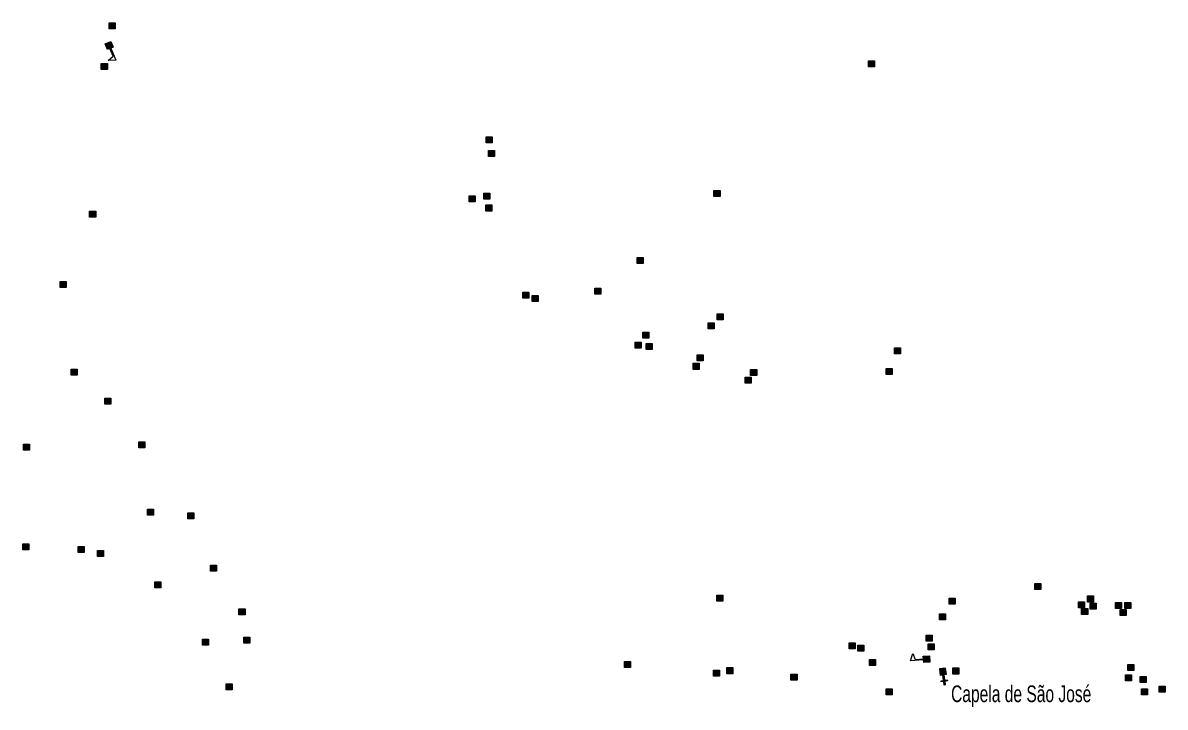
# Model space of a CAD drawing. Extents: x 649.2 to 674.4, y 7040 to 7068.1.
# Drawn here: x 656.02 to 661.51, y 7043.6 to 7046.89 of the extents above; entities that cross this region are included whole.
import ezdxf

# ---------------------------------------------------------------- set-up
doc = ezdxf.new("R2010")
doc.units = 0
doc.header["$LTSCALE"] = 0.032
for name, color, linetype, lineweight in [('2', 7, 'Continuous', 25), ('4', 7, 'Continuous', 25), ('6', 7, 'Continuous', 25)]:
    doc.layers.add(name, color=color, linetype=linetype, lineweight=lineweight)
doc.layers.add('61', color=7, linetype='Continuous')

msp = doc.modelspace()

# ---------------------------------------------------------------- hatches: boundary and pattern name
at = {"layer": '2'}
for points in [[(656.4322, 7046.8861), (656.4612, 7046.8861), (656.4612, 7046.8571), (656.4322, 7046.8571)], [(660.0846, 7046.7032), (660.1136, 7046.7032), (660.1136, 7046.6742), (660.0846, 7046.6742)], [(656.3943, 7046.6907), (656.4233, 7046.6907), (656.4233, 7046.6617), (656.3943, 7046.6617)], [(658.2456, 7046.3383), (658.2746, 7046.3383), (658.2746, 7046.3093), (658.2456, 7046.3093)], [(658.257, 7046.2729), (658.286, 7046.2729), (658.286, 7046.2439), (658.257, 7046.2439)], [(658.1636, 7046.0539), (658.1926, 7046.0539), (658.1926, 7046.0249), (658.1636, 7046.0249)], [(658.2342, 7046.0674), (658.2632, 7046.0674), (658.2632, 7046.0384), (658.2342, 7046.0384)], [(659.3413, 7046.0802), (659.3703, 7046.0802), (659.3703, 7046.0512), (659.3413, 7046.0512)], [(658.2445, 7046.0104), (658.2735, 7046.0104), (658.2735, 7045.9814), (658.2445, 7045.9814)], [(656.3381, 7045.9813), (656.3671, 7045.9813), (656.3671, 7045.9523), (656.3381, 7045.9523)], [(658.9721, 7045.7574), (659.0011, 7045.7574), (659.0011, 7045.7284), (658.9721, 7045.7284)], [(656.1956, 7045.6419), (656.2246, 7045.6419), (656.2246, 7045.6129), (656.1956, 7045.6129)], [(658.7686, 7045.6101), (658.7976, 7045.6101), (658.7976, 7045.5811), (658.7686, 7045.5811)], [(658.4223, 7045.5913), (658.4513, 7045.5913), (658.4513, 7045.5623), (658.4223, 7045.5623)], [(658.4665, 7045.5755), (658.4955, 7045.5755), (658.4955, 7045.5465), (658.4665, 7045.5465)], [(659.3134, 7045.4445), (659.3424, 7045.4445), (659.3424, 7045.4155), (659.3134, 7045.4155)], [(659.3561, 7045.4872), (659.3851, 7045.4872), (659.3851, 7045.4582), (659.3561, 7045.4582)], [(658.9988, 7045.3983), (659.0278, 7045.3983), (659.0278, 7045.3693), (658.9988, 7045.3693)], [(658.9615, 7045.3503), (658.9905, 7045.3503), (658.9905, 7045.3213), (658.9615, 7045.3213)], [(659.0148, 7045.345), (659.0438, 7045.345), (659.0438, 7045.316), (659.0148, 7045.316)], [(660.2099, 7045.3236), (660.2389, 7045.3236), (660.2389, 7045.2946), (660.2099, 7045.2946)], [(659.2601, 7045.2899), (659.2891, 7045.2899), (659.2891, 7045.2609), (659.2601, 7045.2609)], [(656.2492, 7045.2208), (656.2782, 7045.2208), (656.2782, 7045.1918), (656.2492, 7045.1918)], [(659.2405, 7045.249), (659.2695, 7045.249), (659.2695, 7045.22), (659.2405, 7045.22)], [(659.5178, 7045.2188), (659.5468, 7045.2188), (659.5468, 7045.1898), (659.5178, 7045.1898)], [(660.1698, 7045.2245), (660.1988, 7045.2245), (660.1988, 7045.1955), (660.1698, 7045.1955)], [(659.4912, 7045.1832), (659.5202, 7045.1832), (659.5202, 7045.1542), (659.4912, 7045.1542)], [(656.4106, 7045.0809), (656.4396, 7045.0809), (656.4396, 7045.0519), (656.4106, 7045.0519)], [(656.0198, 7044.8607), (656.0488, 7044.8607), (656.0488, 7044.8317), (656.0198, 7044.8317)], [(656.5748, 7044.8712), (656.6038, 7044.8712), (656.6038, 7044.8422), (656.5748, 7044.8422)], [(656.617, 7044.548), (656.646, 7044.548), (656.646, 7044.519), (656.617, 7044.519)], [(656.8105, 7044.5296), (656.8395, 7044.5296), (656.8395, 7044.5006), (656.8105, 7044.5006)], [(656.0168, 7044.3813), (656.0458, 7044.3813), (656.0458, 7044.3523), (656.0168, 7044.3523)], [(656.2822, 7044.3681), (656.3112, 7044.3681), (656.3112, 7044.3391), (656.2822, 7044.3391)], [(656.3757, 7044.3496), (656.4047, 7044.3496), (656.4047, 7044.3206), (656.3757, 7044.3206)], [(656.9187, 7044.2781), (656.9477, 7044.2781), (656.9477, 7044.2491), (656.9187, 7044.2491)], [(656.6519, 7044.1983), (656.6809, 7044.1983), (656.6809, 7044.1693), (656.6519, 7044.1693)], [(660.8851, 7044.1906), (660.9141, 7044.1906), (660.9141, 7044.1616), (660.8851, 7044.1616)], [(659.3543, 7044.1338), (659.3833, 7044.1338), (659.3833, 7044.1048), (659.3543, 7044.1048)], [(660.473, 7044.1199), (660.502, 7044.1199), (660.502, 7044.0909), (660.473, 7044.0909)], [(661.1374, 7044.1304), (661.1664, 7044.1304), (661.1664, 7044.1014), (661.1374, 7044.1014)], [(657.0565, 7044.0681), (657.0855, 7044.0681), (657.0855, 7044.0391), (657.0565, 7044.0391)], [(661.0943, 7044.1017), (661.1233, 7044.1017), (661.1233, 7044.0727), (661.0943, 7044.0727)], [(661.11, 7044.0703), (661.139, 7044.0703), (661.139, 7044.0413), (661.11, 7044.0413)], [(661.1505, 7044.0964), (661.1795, 7044.0964), (661.1795, 7044.0674), (661.1505, 7044.0674)], [(661.2721, 7044.0991), (661.3011, 7044.0991), (661.3011, 7044.0701), (661.2721, 7044.0701)], [(661.2957, 7044.0651), (661.3247, 7044.0651), (661.3247, 7044.0361), (661.2957, 7044.0361)], [(661.3179, 7044.0991), (661.3469, 7044.0991), (661.3469, 7044.0701), (661.3179, 7044.0701)], [(660.4258, 7044.0453), (660.4548, 7044.0453), (660.4548, 7044.0163), (660.4258, 7044.0163)], [(656.8809, 7043.9231), (656.9099, 7043.9231), (656.9099, 7043.8941), (656.8809, 7043.8941)], [(657.0804, 7043.9327), (657.1094, 7043.9327), (657.1094, 7043.9037), (657.0804, 7043.9037)], [(659.9916, 7043.9047), (660.0206, 7043.9047), (660.0206, 7043.8757), (659.9916, 7043.8757)], [(660.3623, 7043.942), (660.3913, 7043.942), (660.3913, 7043.913), (660.3623, 7043.913)], [(660.371, 7043.901), (660.4, 7043.901), (660.4, 7043.872), (660.371, 7043.872)], [(660.0327, 7043.8935), (660.0617, 7043.8935), (660.0617, 7043.8645), (660.0327, 7043.8645)], [(658.9113, 7043.8151), (658.9403, 7043.8151), (658.9403, 7043.7861), (658.9113, 7043.7861)], [(659.4033, 7043.7858), (659.4323, 7043.7858), (659.4323, 7043.7568), (659.4033, 7043.7568)], [(660.0899, 7043.8251), (660.1189, 7043.8251), (660.1189, 7043.7961), (660.0899, 7043.7961)], [(661.3323, 7043.8009), (661.3613, 7043.8009), (661.3613, 7043.7719), (661.3323, 7043.7719)], [(659.3392, 7043.7736), (659.3682, 7043.7736), (659.3682, 7043.7446), (659.3392, 7043.7446)], [(659.7117, 7043.7547), (659.7407, 7043.7547), (659.7407, 7043.7257), (659.7117, 7043.7257)], [(660.4905, 7043.7841), (660.5195, 7043.7841), (660.5195, 7043.7551), (660.4905, 7043.7551)], [(661.3205, 7043.7512), (661.3495, 7043.7512), (661.3495, 7043.7222), (661.3205, 7043.7222)], [(661.3911, 7043.7434), (661.4201, 7043.7434), (661.4201, 7043.7144), (661.3911, 7043.7144)], [(656.9948, 7043.7086), (657.0238, 7043.7086), (657.0238, 7043.6796), (656.9948, 7043.6796)], [(660.1695, 7043.6845), (660.1985, 7043.6845), (660.1985, 7043.6555), (660.1695, 7043.6555)], [(661.3976, 7043.6833), (661.4266, 7043.6833), (661.4266, 7043.6543), (661.3976, 7043.6543)], [(661.4826, 7043.6963), (661.5116, 7043.6963), (661.5116, 7043.6673), (661.4826, 7043.6673)]]:
    msp.add_hatch(color=256, dxfattribs=at).paths.add_polyline_path(points)
at = {"layer": '4'}
for points in [[(656.4403, 7046.7965), (656.452, 7046.7688), (656.4244, 7046.7572), (656.4127, 7046.7848)], [(660.3804, 7043.8126), (660.3505, 7043.8105), (660.3483, 7043.8404), (660.3782, 7043.8426)]]:
    msp.add_hatch(color=256, dxfattribs=at).paths.add_polyline_path(points)
at = {"layer": '6'}
for points in [[(660.4594, 7043.7538), (660.4552, 7043.7835), (660.4255, 7043.7793), (660.4297, 7043.7496)], [(660.442, 7043.7514), (660.447, 7043.7521), (660.4508, 7043.7248), (660.4632, 7043.7266), (660.4639, 7043.7216), (660.4515, 7043.7199), (660.454, 7043.7026), (660.449, 7043.7019), (660.4466, 7043.7192), (660.4342, 7043.7174), (660.4335, 7043.7224), (660.4459, 7043.7241)]]:
    msp.add_hatch(color=256, dxfattribs=at).paths.add_polyline_path(points)

# ---------------------------------------------------------------- linework, layer by layer
at = {"layer": '2'}
for points in [[(656.4322, 7046.8861), (656.4612, 7046.8861), (656.4612, 7046.8571), (656.4322, 7046.8571)], [(660.0846, 7046.7032), (660.1136, 7046.7032), (660.1136, 7046.6742), (660.0846, 7046.6742)], [(656.3943, 7046.6907), (656.4233, 7046.6907), (656.4233, 7046.6617), (656.3943, 7046.6617)], [(658.2456, 7046.3383), (658.2746, 7046.3383), (658.2746, 7046.3093), (658.2456, 7046.3093)], [(658.257, 7046.2729), (658.286, 7046.2729), (658.286, 7046.2439), (658.257, 7046.2439)], [(658.1636, 7046.0539), (658.1926, 7046.0539), (658.1926, 7046.0249), (658.1636, 7046.0249)], [(658.2342, 7046.0674), (658.2632, 7046.0674), (658.2632, 7046.0384), (658.2342, 7046.0384)], [(659.3413, 7046.0802), (659.3703, 7046.0802), (659.3703, 7046.0512), (659.3413, 7046.0512)], [(658.2445, 7046.0104), (658.2735, 7046.0104), (658.2735, 7045.9814), (658.2445, 7045.9814)], [(656.3381, 7045.9813), (656.3671, 7045.9813), (656.3671, 7045.9523), (656.3381, 7045.9523)], [(658.9721, 7045.7574), (659.0011, 7045.7574), (659.0011, 7045.7284), (658.9721, 7045.7284)], [(656.1956, 7045.6419), (656.2246, 7045.6419), (656.2246, 7045.6129), (656.1956, 7045.6129)], [(658.7686, 7045.6101), (658.7976, 7045.6101), (658.7976, 7045.5811), (658.7686, 7045.5811)], [(658.4223, 7045.5913), (658.4513, 7045.5913), (658.4513, 7045.5623), (658.4223, 7045.5623)], [(658.4665, 7045.5755), (658.4955, 7045.5755), (658.4955, 7045.5465), (658.4665, 7045.5465)], [(659.3134, 7045.4445), (659.3424, 7045.4445), (659.3424, 7045.4155), (659.3134, 7045.4155)], [(659.3561, 7045.4872), (659.3851, 7045.4872), (659.3851, 7045.4582), (659.3561, 7045.4582)], [(658.9988, 7045.3983), (659.0278, 7045.3983), (659.0278, 7045.3693), (658.9988, 7045.3693)], [(658.9615, 7045.3503), (658.9905, 7045.3503), (658.9905, 7045.3213), (658.9615, 7045.3213)], [(659.0148, 7045.345), (659.0438, 7045.345), (659.0438, 7045.316), (659.0148, 7045.316)], [(660.2099, 7045.3236), (660.2389, 7045.3236), (660.2389, 7045.2946), (660.2099, 7045.2946)], [(659.2601, 7045.2899), (659.2891, 7045.2899), (659.2891, 7045.2609), (659.2601, 7045.2609)], [(656.2492, 7045.2208), (656.2782, 7045.2208), (656.2782, 7045.1918), (656.2492, 7045.1918)], [(659.2405, 7045.249), (659.2695, 7045.249), (659.2695, 7045.22), (659.2405, 7045.22)], [(659.5178, 7045.2188), (659.5468, 7045.2188), (659.5468, 7045.1898), (659.5178, 7045.1898)], [(660.1698, 7045.2245), (660.1988, 7045.2245), (660.1988, 7045.1955), (660.1698, 7045.1955)], [(659.4912, 7045.1832), (659.5202, 7045.1832), (659.5202, 7045.1542), (659.4912, 7045.1542)], [(656.4106, 7045.0809), (656.4396, 7045.0809), (656.4396, 7045.0519), (656.4106, 7045.0519)], [(656.0198, 7044.8607), (656.0488, 7044.8607), (656.0488, 7044.8317), (656.0198, 7044.8317)], [(656.5748, 7044.8712), (656.6038, 7044.8712), (656.6038, 7044.8422), (656.5748, 7044.8422)], [(656.617, 7044.548), (656.646, 7044.548), (656.646, 7044.519), (656.617, 7044.519)], [(656.8105, 7044.5296), (656.8395, 7044.5296), (656.8395, 7044.5006), (656.8105, 7044.5006)], [(656.0168, 7044.3813), (656.0458, 7044.3813), (656.0458, 7044.3523), (656.0168, 7044.3523)], [(656.2822, 7044.3681), (656.3112, 7044.3681), (656.3112, 7044.3391), (656.2822, 7044.3391)], [(656.3757, 7044.3496), (656.4047, 7044.3496), (656.4047, 7044.3206), (656.3757, 7044.3206)], [(656.9187, 7044.2781), (656.9477, 7044.2781), (656.9477, 7044.2491), (656.9187, 7044.2491)], [(656.6519, 7044.1983), (656.6809, 7044.1983), (656.6809, 7044.1693), (656.6519, 7044.1693)], [(660.8851, 7044.1906), (660.9141, 7044.1906), (660.9141, 7044.1616), (660.8851, 7044.1616)], [(659.3543, 7044.1338), (659.3833, 7044.1338), (659.3833, 7044.1048), (659.3543, 7044.1048)], [(660.473, 7044.1199), (660.502, 7044.1199), (660.502, 7044.0909), (660.473, 7044.0909)], [(661.1374, 7044.1304), (661.1664, 7044.1304), (661.1664, 7044.1014), (661.1374, 7044.1014)], [(657.0565, 7044.0681), (657.0855, 7044.0681), (657.0855, 7044.0391), (657.0565, 7044.0391)], [(661.0943, 7044.1017), (661.1233, 7044.1017), (661.1233, 7044.0727), (661.0943, 7044.0727)], [(661.11, 7044.0703), (661.139, 7044.0703), (661.139, 7044.0413), (661.11, 7044.0413)], [(661.1505, 7044.0964), (661.1795, 7044.0964), (661.1795, 7044.0674), (661.1505, 7044.0674)], [(661.2721, 7044.0991), (661.3011, 7044.0991), (661.3011, 7044.0701), (661.2721, 7044.0701)], [(661.2957, 7044.0651), (661.3247, 7044.0651), (661.3247, 7044.0361), (661.2957, 7044.0361)], [(661.3179, 7044.0991), (661.3469, 7044.0991), (661.3469, 7044.0701), (661.3179, 7044.0701)], [(660.4258, 7044.0453), (660.4548, 7044.0453), (660.4548, 7044.0163), (660.4258, 7044.0163)], [(656.8809, 7043.9231), (656.9099, 7043.9231), (656.9099, 7043.8941), (656.8809, 7043.8941)], [(657.0804, 7043.9327), (657.1094, 7043.9327), (657.1094, 7043.9037), (657.0804, 7043.9037)], [(659.9916, 7043.9047), (660.0206, 7043.9047), (660.0206, 7043.8757), (659.9916, 7043.8757)], [(660.3623, 7043.942), (660.3913, 7043.942), (660.3913, 7043.913), (660.3623, 7043.913)], [(660.371, 7043.901), (660.4, 7043.901), (660.4, 7043.872), (660.371, 7043.872)], [(660.0327, 7043.8935), (660.0617, 7043.8935), (660.0617, 7043.8645), (660.0327, 7043.8645)], [(658.9113, 7043.8151), (658.9403, 7043.8151), (658.9403, 7043.7861), (658.9113, 7043.7861)], [(659.4033, 7043.7858), (659.4323, 7043.7858), (659.4323, 7043.7568), (659.4033, 7043.7568)], [(660.0899, 7043.8251), (660.1189, 7043.8251), (660.1189, 7043.7961), (660.0899, 7043.7961)], [(661.3323, 7043.8009), (661.3613, 7043.8009), (661.3613, 7043.7719), (661.3323, 7043.7719)], [(659.3392, 7043.7736), (659.3682, 7043.7736), (659.3682, 7043.7446), (659.3392, 7043.7446)], [(659.7117, 7043.7547), (659.7407, 7043.7547), (659.7407, 7043.7257), (659.7117, 7043.7257)], [(660.4905, 7043.7841), (660.5195, 7043.7841), (660.5195, 7043.7551), (660.4905, 7043.7551)], [(661.3205, 7043.7512), (661.3495, 7043.7512), (661.3495, 7043.7222), (661.3205, 7043.7222)], [(661.3911, 7043.7434), (661.4201, 7043.7434), (661.4201, 7043.7144), (661.3911, 7043.7144)], [(656.9948, 7043.7086), (657.0238, 7043.7086), (657.0238, 7043.6796), (656.9948, 7043.6796)], [(660.1695, 7043.6845), (660.1985, 7043.6845), (660.1985, 7043.6555), (660.1695, 7043.6555)], [(661.3976, 7043.6833), (661.4266, 7043.6833), (661.4266, 7043.6543), (661.3976, 7043.6543)], [(661.4826, 7043.6963), (661.5116, 7043.6963), (661.5116, 7043.6673), (661.4826, 7043.6673)]]:
    msp.add_lwpolyline(points, close=True, dxfattribs=at)
at = {"layer": '4'}
for p, q in [((656.4405, 7046.764), (656.4359, 7046.762)), ((660.3496, 7043.8229), (660.3492, 7043.8279))]:
    msp.add_line(p, q, dxfattribs=at)
for points in [[(656.4403, 7046.7965), (656.452, 7046.7688), (656.4244, 7046.7572), (656.4127, 7046.7848)], [(656.4405, 7046.764), (656.4648, 7046.7064), (656.4277, 7046.7043), (656.4513, 7046.7256), (656.4359, 7046.762)], [(660.3496, 7043.8229), (660.2872, 7043.8184), (660.2972, 7043.8542), (660.3098, 7043.825), (660.3492, 7043.8279)], [(660.3804, 7043.8126), (660.3505, 7043.8105), (660.3483, 7043.8404), (660.3782, 7043.8426)]]:
    msp.add_lwpolyline(points, close=True, dxfattribs=at)
at = {"layer": '6'}
for points in [[(660.4594, 7043.7538), (660.4552, 7043.7835), (660.4255, 7043.7793), (660.4297, 7043.7496)], [(660.442, 7043.7514), (660.447, 7043.7521), (660.4508, 7043.7248), (660.4632, 7043.7266), (660.4639, 7043.7216), (660.4515, 7043.7199), (660.454, 7043.7026), (660.449, 7043.7019), (660.4466, 7043.7192), (660.4342, 7043.7174), (660.4335, 7043.7224), (660.4459, 7043.7241)]]:
    msp.add_lwpolyline(points, close=True, dxfattribs=at)

# ---------------------------------------------------------------- texts
at = {"layer": '61', "width": 0.7}
msp.add_text('Capela de São José', height=0.08, dxfattribs=at).set_placement((660.4819, 7043.62))

doc.saveas('drawing.dxf')
